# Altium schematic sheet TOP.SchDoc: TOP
size A4; Author: Silvio Navaretti; CompanyName: Arduino srl; DocumentNumber: ABX00063; Revision: V1.2; SheetNumber: 1; SheetTotal: 8; RevAuthor: Silvio Navaretti
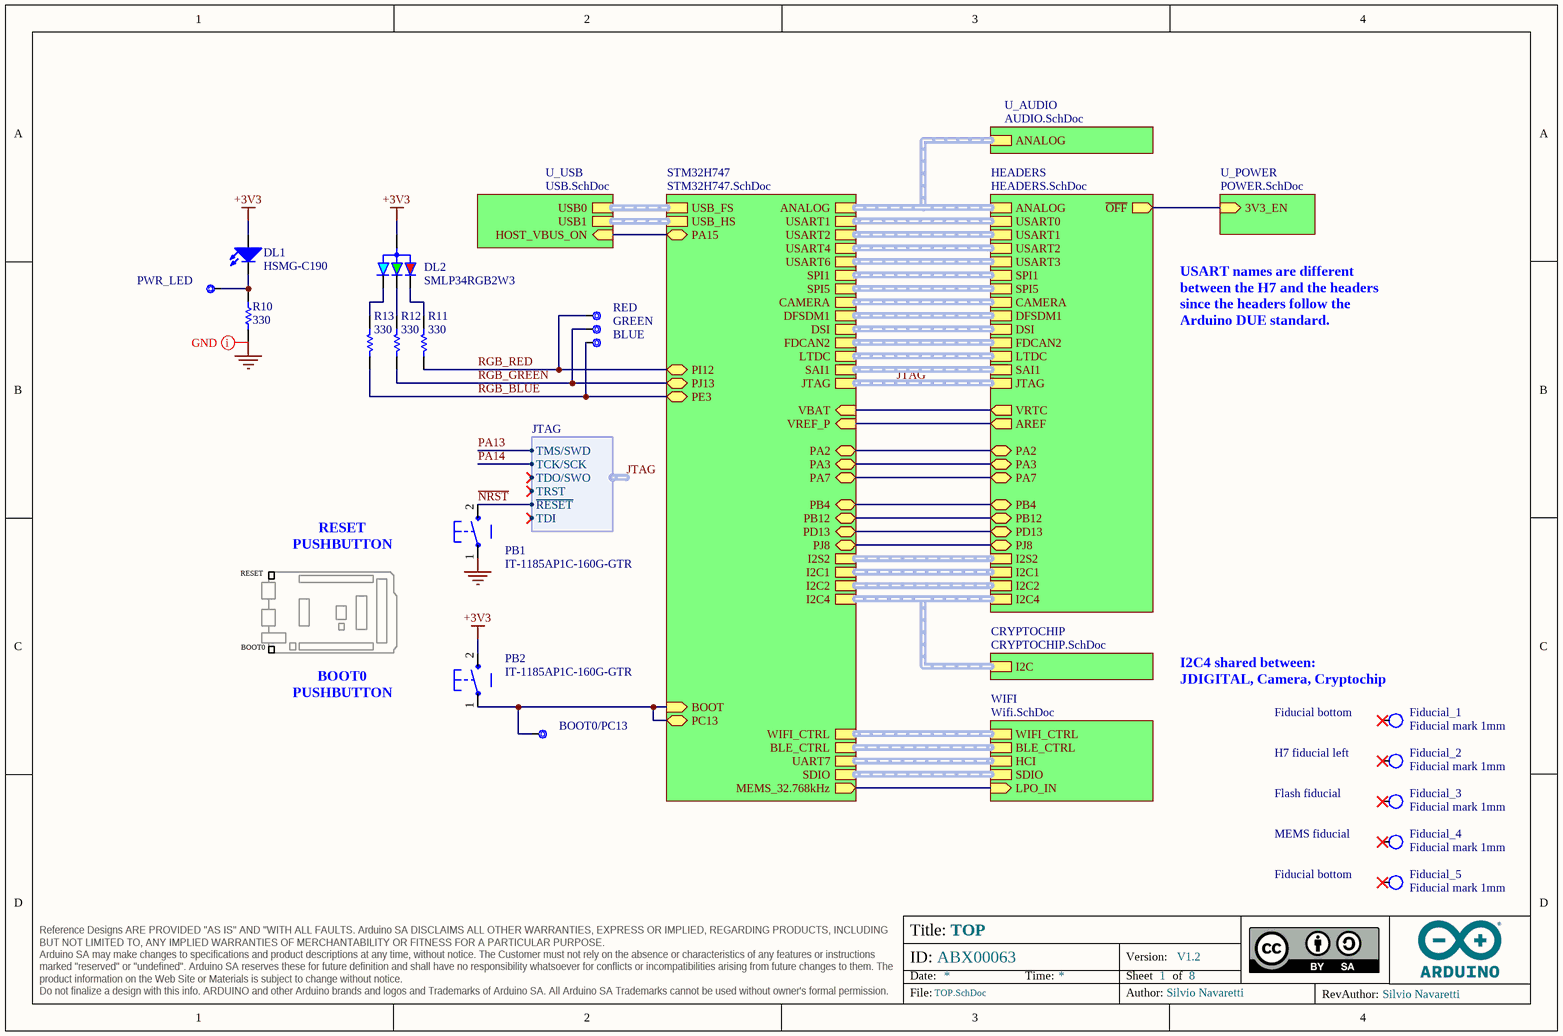
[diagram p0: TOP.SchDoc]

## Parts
BLUE  CMP-018-0005-A.3  [TP-1.00MM]  (value not drawn)  (no BOM)
BOOT0/PC13  CMP-018-0005-A.3  [TP-1.00MM]  (value not drawn)  (no BOM)
DL1  HSMG-C190  [LEDC1608X80N-AK]
DL2  SMLP34RGB2W3  [SMLP34RGB2W]
Fiducial_1  Fiducial mark 1mm  [Fiducial mark 1mm-Footprint-1]  (no BOM)
Fiducial_2  Fiducial mark 1mm  [Fiducial mark 1mm-Footprint-1]  (no BOM)
Fiducial_3  Fiducial mark 1mm  [Fiducial mark 1mm-Footprint-1]  (no BOM)
Fiducial_4  Fiducial mark 1mm  [Fiducial mark 1mm-Footprint-1]  (no BOM)
Fiducial_5  Fiducial mark 1mm  [Fiducial mark 1mm-Footprint-1]  (no BOM)
GREEN  CMP-018-0005-A.3  [TP-1.00MM]  (value not drawn)  (no BOM)
PB1  IT-1185AP1C-160G-GTR  [C&K_PTS820_NO_HOLES-1]
PB2  IT-1185AP1C-160G-GTR  [C&K_PTS820_NO_HOLES-1]
PWR_LED  CMP-018-0005-A.3  [TP-1.00MM]  (value not drawn)  (no BOM)
R10  value 330  [RES-0402]  (hidden comment: CRCW0402330RJNED)
R11  value 330  [RES-0402]  (hidden comment: CRCW0402330RJNED)
R12  value 330  [RES-0402]  (hidden comment: CRCW0402330RJNED)
R13  value 330  [RES-0402]  (hidden comment: CRCW0402330RJNED)
RED  CMP-018-0005-A.3  [TP-1.00MM]  (value not drawn)  (no BOM)

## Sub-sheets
CRYPTOCHIP = CRYPTOCHIP.SchDoc: I2C (harness I2C)
HEADERS = HEADERS.SchDoc: SPI5 (harness SPI), PB4 (bidir), I2C1 (harness I2C), LTDC (harness LTDC), SAI1 (harness SAI), I2C4 (harness I2C), USART0 (harness UART), USART3 (harness UART), USART2 (harness UART), USART1 (harness UART), I2C2 (harness I2C), PD13 (bidir), PA7 (bidir), PJ8 (bidir), PA2 (bidir), PA3 (bidir), ANALOG (harness ANALOG), FDCAN2 (harness FDCAN), I2S2 (harness I2S), DSI (harness DISPLAY), DFSDM1 (harness DFSDM), SPI1 (harness SPI), CAMERA (harness ARDUCAM), AREF (out), ~{OFF} (out), VRTC (out), JTAG (harness JTAG), PB12 (bidir)
STM32H747 = STM32H747.SchDoc: BOOT (in), DSI (harness DISPLAY), VREF_P (in), SDIO (harness SDC), USB_FS (harness USB), USB_HS (harness USB), PI12 (bidir), PE3 (bidir), PJ13 (bidir), UART7 (harness UART), PC13 (bidir), I2C1 (harness I2C), USART1 (harness UART), USART6 (harness UART), USART4 (harness UART), USART2 (harness UART), I2C2 (harness I2C), ANALOG (harness ANALOG), FDCAN2 (harness FDCAN), LTDC (harness LTDC), SAI1 (harness SAI), I2S2 (harness I2S), DFSDM1 (harness DFSDM), I2C4 (harness I2C), CAMERA (harness ARDUCAM), SPI5 (harness SPI), SPI1 (harness SPI), BLE_CTRL (harness BLE CTRL), WIFI_CTRL (harness WiFi CTRL), PD13 (bidir), PB4 (bidir), PA7 (bidir), PJ8 (bidir), PA2 (bidir), PA3 (bidir), JTAG (harness JTAG), PB12 (bidir), VBAT (in), MEMS_32.768kHz (out), PA15 (bidir)
U_AUDIO = AUDIO.SchDoc: ANALOG (harness ANALOG)
U_POWER = POWER.SchDoc: 3V3_EN (in)
U_USB = USB.SchDoc: USB0 (harness USB), USB1 (harness USB), HOST_VBUS_ON (in)
WIFI = Wifi.SchDoc: BLE_CTRL (harness BLE CTRL), HCI (harness UART), WIFI_CTRL (harness WiFi CTRL), SDIO (harness SDC), LPO_IN (in)

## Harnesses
JTAG: ~{RESET}, TCK/SCK, TDI, TDO/SWO, TMS/SWD, TRST

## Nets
+3V3: DL1.A DL2.1(ANODE) PB2.2
GND: PB1.1 R10.1
~{NRST}: PB1.2 ; sheet STM32H747/JTAG.~{RESET}  [project net JTAG.~{RESET}]
RGB_BLUE: BLUE.X R13.2 ; sheet STM32H747/PE3
RGB_GREEN: GREEN.X R12.2 ; sheet STM32H747/PJ13
RGB_RED: R11.2 RED.X ; sheet STM32H747/PI12
NetBOOT0/PC13_X: BOOT0/PC13.X PB2.1 ; sheet STM32H747/BOOT, sheet STM32H747/PC13
NetDL1_C: DL1.C PWR_LED.X R10.2
NetDL2_2: DL2.2(RED_C) R11.1
NetDL2_3: DL2.3(BLUE_C) R13.1
NetDL2_4: DL2.4(GREEN_C) R12.1
(unnamed): sheet U_POWER/3V3_EN, sheet HEADERS/~{OFF}
(unnamed): sheet U_USB/HOST_VBUS_ON, sheet STM32H747/PA15  [a separate net that carries the same name]
(unnamed): sheet STM32H747/VREF_P, sheet HEADERS/AREF  [a separate net that carries the same name]
(unnamed): sheet STM32H747/PD13, sheet HEADERS/PD13  [a separate net that carries the same name]
(unnamed): sheet STM32H747/PB4, sheet HEADERS/PB4  [a separate net that carries the same name]
(unnamed): sheet STM32H747/PA7, sheet HEADERS/PA7  [a separate net that carries the same name]
(unnamed): sheet STM32H747/PJ8, sheet HEADERS/PJ8  [a separate net that carries the same name]
(unnamed): sheet STM32H747/PA2, sheet HEADERS/PA2  [a separate net that carries the same name]
(unnamed): sheet STM32H747/PA3, sheet HEADERS/PA3  [a separate net that carries the same name]
(unnamed): sheet STM32H747/PB12, sheet HEADERS/PB12  [a separate net that carries the same name]
(unnamed): sheet STM32H747/VBAT, sheet HEADERS/VRTC  [a separate net that carries the same name]
(unnamed): sheet STM32H747/MEMS_32.768kHz, sheet WIFI/LPO_IN  [a separate net that carries the same name]

Not connected (* = marked no-connect by the designer): Fiducial_1 1*; Fiducial_2 1*; Fiducial_3 1*; Fiducial_4 1*; Fiducial_5 1*

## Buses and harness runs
harness JTAG = sheet HEADERS/JTAG = sheet STM32H747/JTAG
harness sheet CRYPTOCHIP/I2C = sheet HEADERS/I2C4 = sheet STM32H747/I2C4
harness sheet HEADERS/ANALOG = sheet STM32H747/ANALOG = sheet U_AUDIO/ANALOG
harness sheet HEADERS/CAMERA = sheet STM32H747/CAMERA
harness sheet HEADERS/DFSDM1 = sheet STM32H747/DFSDM1
harness sheet HEADERS/DSI = sheet STM32H747/DSI
harness sheet HEADERS/FDCAN2 = sheet STM32H747/FDCAN2
harness sheet HEADERS/I2C1 = sheet STM32H747/I2C1
harness sheet HEADERS/I2C2 = sheet STM32H747/I2C2
harness sheet HEADERS/I2S2 = sheet STM32H747/I2S2
harness sheet HEADERS/LTDC = sheet STM32H747/LTDC
harness sheet HEADERS/SAI1 = sheet STM32H747/SAI1
harness sheet HEADERS/SPI1 = sheet STM32H747/SPI1
harness sheet HEADERS/SPI5 = sheet STM32H747/SPI5
harness sheet HEADERS/USART0 = sheet STM32H747/USART1
harness sheet HEADERS/USART1 = sheet STM32H747/USART2
harness sheet HEADERS/USART2 = sheet STM32H747/USART4
harness sheet HEADERS/USART3 = sheet STM32H747/USART6
harness sheet STM32H747/BLE_CTRL = sheet WIFI/BLE_CTRL
harness sheet STM32H747/SDIO = sheet WIFI/SDIO
harness sheet STM32H747/UART7 = sheet WIFI/HCI
harness sheet STM32H747/USB_FS = sheet U_USB/USB0
harness sheet STM32H747/USB_HS = sheet U_USB/USB1
harness sheet STM32H747/WIFI_CTRL = sheet WIFI/WIFI_CTRL

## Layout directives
net class GND: GND

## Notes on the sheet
- USART names are different between the H7 and the headers since the headers follow the Arduino DUE standard.
- RESET
- RESET
  PUSHBUTTON
- BOOT0
- BOOT0
  PUSHBUTTON
- (near Fiducial_1) I2C4 shared between:
  JDIGITAL, Camera, Cryptochip
- (near Fiducial_1) Fiducial bottom
- (near Fiducial_2) H7 fiducial left
- Flash fiducial
- MEMS fiducial
- Fiducial bottom

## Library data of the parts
BLUE BOOT0/PC13 GREEN PWR_LED RED = UT0013-A.4: Test point 1.00mm
DL1 = L0009-A.4: LED SMD 0603 GREEN/568 15mcd 120^; Manufacturer: Broadcom; Code Arduino: 2204
DL2 = L0014-A.9: LED RGB DIFFUSED PICOLED SMD; Manufacturer: ROHM Semiconductor; Code Arduino: A5469; Test Current: 5mA; Dominant Wavelength: 470nm; Lens Color: White; Lens Style: Rectangular; Forward Voltage: 3V; Luminous Intensity: 45mcd; Forward Current: 20mA
Fiducial_1-Fiducial_5 = UT0023-A.6: Fiducial mark 1mm clearance 2mm
PB1 PB2 = B0001-A.7: PUSHBUTTON WHITE NO ANCHORS; Manufacturer: Switronic; Code Arduino: 0173
R10-R13 = R0017-A.15: RES CHIP 0402 330R 5% 1/16W; Manufacturer: Vishay; Power: 63mW; Code Arduino: 2229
